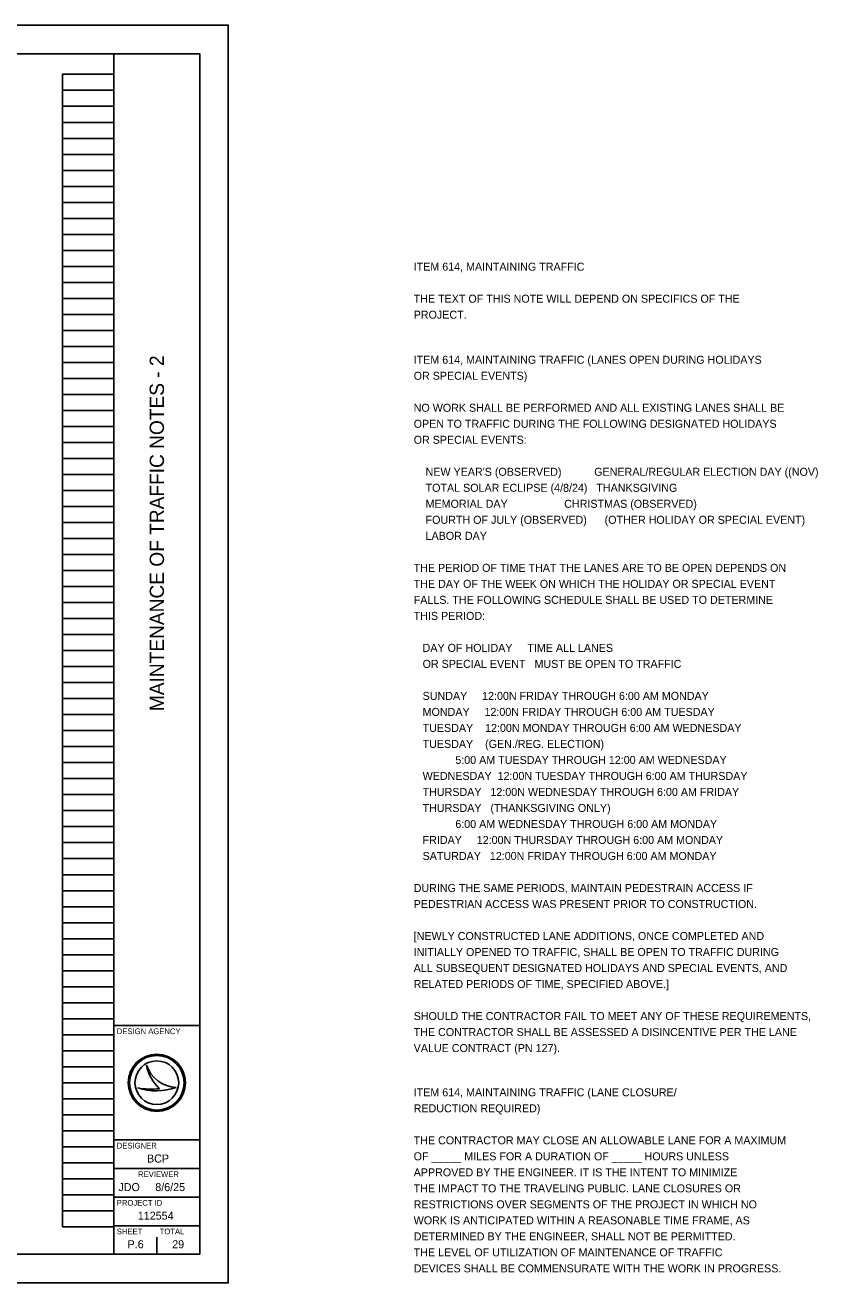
# Model space of a CAD drawing. Extents: x -59 to 65, y -12 to 46.
# Drawn here: x 30.45 to 44.31, y 0 to 22 of the extents above; entities that cross this region are included whole.
import ezdxf

# ---------------------------------------------------------------- set-up
doc = ezdxf.new("R2010")
doc.units = 0
for name, color, linetype in [('SH_Border', 7, 'Continuous'), ('SH_Cut_Line', 7, 'Continuous'), ('SH_Data', 7, 'Continuous'), ('SH_Text', 7, 'Continuous')]:
    doc.layers.add(name, color=color, linetype=linetype)

msp = doc.modelspace()

# ---------------------------------------------------------------- linework, layer by layer
at = {"layer": 'SH_Border'}
for p, q in [((32, 0.5), (32, 21.5)), ((32, 4.5), (33.5, 4.5)), ((32, 2.5), (33.5, 2.5)), ((32, 2), (33.5, 2)), ((32, 1.5), (33.5, 1.5)), ((32, 1), (33.5, 1))]:
    msp.add_line(p, q, dxfattribs=at)
msp.add_lwpolyline([(1.5, 21.5), (33.5, 21.5), (33.5, 0.5), (1.5, 0.5)], close=True, dxfattribs=at)
at = {"layer": 'SH_Cut_Line'}
msp.add_lwpolyline([(0, 0), (34, 0), (34, 22), (0, 22)], close=True, dxfattribs=at)
at = {"layer": 'SH_Data'}
for p, q in [((31.1, 0.98), (31.1, 21.14)), ((31.1, 21.14), (32, 21.14)), ((32, 0.98), (32, 21.14)), ((31.1, 20.86), (32, 20.86)), ((31.1, 20.58), (32, 20.58)), ((31.1, 20.3), (32, 20.3)), ((31.1, 20.02), (32, 20.02)), ((31.1, 19.74), (32, 19.74)), ((31.1, 19.46), (32, 19.46)), ((31.1, 19.18), (32, 19.18)), ((31.1, 18.9), (32, 18.9)), ((31.1, 18.62), (32, 18.62)), ((31.1, 18.34), (32, 18.34)), ((31.1, 18.06), (32, 18.06)), ((31.1, 17.78), (32, 17.78)), ((31.1, 17.5), (32, 17.5)), ((31.1, 17.22), (32, 17.22)), ((31.1, 16.94), (32, 16.94)), ((31.1, 16.66), (32, 16.66)), ((31.1, 16.38), (32, 16.38)), ((31.1, 16.1), (32, 16.1)), ((31.1, 15.82), (32, 15.82)), ((31.1, 15.54), (32, 15.54)), ((31.1, 15.26), (32, 15.26)), ((31.1, 14.98), (32, 14.98)), ((31.1, 14.7), (32, 14.7)), ((31.1, 14.42), (32, 14.42)), ((31.1, 14.14), (32, 14.14)), ((31.1, 13.86), (32, 13.86)), ((31.1, 13.58), (32, 13.58)), ((31.1, 13.3), (32, 13.3)), ((31.1, 13.02), (32, 13.02)), ((31.1, 12.74), (32, 12.74)), ((31.1, 12.46), (32, 12.46)), ((31.1, 12.18), (32, 12.18)), ((31.1, 11.9), (32, 11.9)), ((31.1, 11.62), (32, 11.62)), ((31.1, 11.34), (32, 11.34)), ((31.1, 11.06), (32, 11.06)), ((31.1, 10.78), (32, 10.78)), ((31.1, 10.5), (32, 10.5)), ((31.1, 10.22), (32, 10.22)), ((31.1, 9.94), (32, 9.94)), ((31.1, 9.66), (32, 9.66)), ((31.1, 9.38), (32, 9.38)), ((31.1, 9.1), (32, 9.1)), ((31.1, 8.82), (32, 8.82)), ((31.1, 8.54), (32, 8.54)), ((31.1, 8.26), (32, 8.26)), ((31.1, 7.98), (32, 7.98)), ((31.1, 7.7), (32, 7.7)), ((31.1, 7.42), (32, 7.42)), ((31.1, 7.14), (32, 7.14)), ((31.1, 6.86), (32, 6.86)), ((31.1, 6.58), (32, 6.58)), ((31.1, 6.3), (32, 6.3)), ((31.1, 6.02), (32, 6.02)), ((31.1, 5.74), (32, 5.74)), ((31.1, 5.46), (32, 5.46)), ((31.1, 5.18), (32, 5.18)), ((31.1, 4.9), (32, 4.9)), ((31.1, 4.62), (32, 4.62)), ((31.1, 4.34), (32, 4.34)), ((31.1, 4.06), (32, 4.06)), ((31.1, 3.78), (32, 3.78)), ((32.567, 3.81), (32.567, 3.81)), ((31.1, 3.5), (32, 3.5)), ((32.417, 3.41), (32.417, 3.41)), ((32.75, 3.5), (32.75, 3.5)), ((33.087, 3.419), (33.087, 3.419)), ((31.1, 3.22), (32, 3.22)), ((31.1, 2.94), (32, 2.94)), ((31.1, 2.66), (32, 2.66)), ((31.1, 2.38), (32, 2.38)), ((31.1, 2.1), (32, 2.1)), ((31.1, 1.82), (32, 1.82)), ((31.1, 1.54), (32, 1.54)), ((31.1, 1.26), (32, 1.26)), ((31.1, 0.98), (32, 0.98)), ((32.375, 0.675), (32.375, 0.675)), ((32.75, 0.5), (32.75, 0.8))]:
    msp.add_line(p, q, dxfattribs=at)
for radius in [0.5, 0.477, 0.477, 0.382]:
    msp.add_circle((32.75, 3.5), radius, dxfattribs=at)
for centre, radius, start, end in [((33.116, 3.998), 0.58, 198.9257, 198.9319), ((33.347, 3.97), 0.796, 191.6379, 191.6421), ((33.116, 3.998), 0.58, 198.9319, 267.1657), ((33.347, 3.97), 0.796, 191.6421, 226.0947), ((32.739, 4.37), 1.013, 251.4576, 290.0832), ((32.648, 4.654), 1.266, 259.4964, 259.4995), ((32.739, 4.37), 1.013, 251.4527, 251.4576), ((32.648, 4.654), 1.266, 259.4995, 276.6672)]:
    msp.add_arc(centre, radius, start, end, dxfattribs=at)

# ---------------------------------------------------------------- texts
msp.add_text('MAINTENANCE OF TRAFFIC NOTES - 2', height=0.25, rotation=90, dxfattribs=at).set_placement((32.875, 10.001))
for s, height, p in [('DESIGN AGENCY', 0.1, (32.05, 4.35)), ('DESIGNER', 0.1, (32.05, 2.35)), ('BCP', 0.14, (32.579, 2.105)), ('REVIEWER', 0.1, (32.422, 1.85)), ('JDO', 0.14, (32.079, 1.605)), ('8/6/25', 0.14, (32.723, 1.605)), ('PROJECT ID', 0.1, (32.05, 1.35)), ('112554', 0.14, (32.418, 1.105)), ('SHEET', 0.1, (32.05, 0.85)), ('TOTAL', 0.1, (32.8, 0.85)), ('P.6', 0.14, (32.239, 0.605)), ('29', 0.14, (33.019, 0.605))]:
    msp.add_text(s, height=height, dxfattribs=at).set_placement(p)
at = {"layer": 'SH_Text'}
for s, p in [('ITEM 614, MAINTAINING TRAFFIC', (37.241, 17.705)), ('THE TEXT OF THIS NOTE WILL DEPEND ON SPECIFICS OF THE', (37.241, 17.145)), ('PROJECT.', (37.241, 16.865)), ('ITEM 614, MAINTAINING TRAFFIC (LANES OPEN DURING HOLIDAYS', (37.241, 16.077)), ('OR SPECIAL EVENTS)', (37.241, 15.797)), ('NO WORK SHALL BE PERFORMED AND ALL EXISTING LANES SHALL BE', (37.241, 15.237)), ('OPEN TO TRAFFIC DURING THE FOLLOWING DESIGNATED HOLIDAYS', (37.241, 14.957)), ('OR SPECIAL EVENTS:', (37.241, 14.677)), ("    NEW YEAR'S (OBSERVED)           GENERAL/REGULAR ELECTION DAY ((NOV)", (37.241, 14.117)), ('    TOTAL SOLAR ECLIPSE (4/8/24)   THANKSGIVING', (37.241, 13.837)), ('    MEMORIAL DAY                   CHRISTMAS (OBSERVED)', (37.241, 13.557)), ('    FOURTH OF JULY (OBSERVED)      (OTHER HOLIDAY OR SPECIAL EVENT)', (37.241, 13.277)), ('    LABOR DAY', (37.241, 12.997)), ('THE PERIOD OF TIME THAT THE LANES ARE TO BE OPEN DEPENDS ON', (37.241, 12.437)), ('THE DAY OF THE WEEK ON WHICH THE HOLIDAY OR SPECIAL EVENT', (37.241, 12.157)), ('FALLS. THE FOLLOWING SCHEDULE SHALL BE USED TO DETERMINE', (37.241, 11.877)), ('THIS PERIOD:', (37.241, 11.597)), ('   DAY OF HOLIDAY     TIME ALL LANES', (37.241, 11.037)), ('   OR SPECIAL EVENT   MUST BE OPEN TO TRAFFIC', (37.241, 10.757)), ('   SUNDAY     12:00N FRIDAY THROUGH 6:00 AM MONDAY', (37.241, 10.197)), ('   MONDAY     12:00N FRIDAY THROUGH 6:00 AM TUESDAY', (37.241, 9.917)), ('   TUESDAY    12:00N MONDAY THROUGH 6:00 AM WEDNESDAY', (37.241, 9.637)), ('   TUESDAY    (GEN./REG. ELECTION)', (37.241, 9.357)), ('              5:00 AM TUESDAY THROUGH 12:00 AM WEDNESDAY', (37.241, 9.077)), ('   WEDNESDAY  12:00N TUESDAY THROUGH 6:00 AM THURSDAY', (37.241, 8.797)), ('   THURSDAY   12:00N WEDNESDAY THROUGH 6:00 AM FRIDAY', (37.241, 8.517)), ('   THURSDAY   (THANKSGIVING ONLY)', (37.241, 8.237)), ('              6:00 AM WEDNESDAY THROUGH 6:00 AM MONDAY', (37.241, 7.957)), ('   FRIDAY     12:00N THURSDAY THROUGH 6:00 AM MONDAY', (37.241, 7.677)), ('   SATURDAY   12:00N FRIDAY THROUGH 6:00 AM MONDAY', (37.241, 7.397)), ('DURING THE SAME PERIODS, MAINTAIN PEDESTRAIN ACCESS IF', (37.241, 6.837)), ('PEDESTRIAN ACCESS WAS PRESENT PRIOR TO CONSTRUCTION.', (37.241, 6.557)), ('[NEWLY CONSTRUCTED LANE ADDITIONS, ONCE COMPLETED AND', (37.241, 5.997)), ('INITIALLY OPENED TO TRAFFIC, SHALL BE OPEN TO TRAFFIC DURING', (37.241, 5.717)), ('ALL SUBSEQUENT DESIGNATED HOLIDAYS AND SPECIAL EVENTS, AND', (37.241, 5.437)), ('RELATED PERIODS OF TIME, SPECIFIED ABOVE.]', (37.241, 5.157)), ('SHOULD THE CONTRACTOR FAIL TO MEET ANY OF THESE REQUIREMENTS,', (37.241, 4.597)), ('THE CONTRACTOR SHALL BE ASSESSED A DISINCENTIVE PER THE LANE', (37.241, 4.317)), ('VALUE CONTRACT (PN 127).', (37.241, 4.037)), ('ITEM 614, MAINTAINING TRAFFIC (LANE CLOSURE/', (37.241, 3.263)), ('REDUCTION REQUIRED)', (37.241, 2.983)), ('THE CONTRACTOR MAY CLOSE AN ALLOWABLE LANE FOR A MAXIMUM', (37.241, 2.423)), ('OF _____ MILES FOR A DURATION OF _____ HOURS UNLESS', (37.241, 2.143)), ('APPROVED BY THE ENGINEER. IT IS THE INTENT TO MINIMIZE', (37.241, 1.863)), ('THE IMPACT TO THE TRAVELING PUBLIC. LANE CLOSURES OR', (37.241, 1.583)), ('RESTRICTIONS OVER SEGMENTS OF THE PROJECT IN WHICH NO', (37.241, 1.303)), ('WORK IS ANTICIPATED WITHIN A REASONABLE TIME FRAME, AS', (37.241, 1.023)), ('DETERMINED BY THE ENGINEER, SHALL NOT BE PERMITTED.', (37.241, 0.743)), ('THE LEVEL OF UTILIZATION OF MAINTENANCE OF TRAFFIC', (37.241, 0.463)), ('DEVICES SHALL BE COMMENSURATE WITH THE WORK IN PROGRESS.', (37.241, 0.183))]:
    msp.add_text(s, height=0.14, dxfattribs=at).set_placement(p)

doc.saveas('drawing.dxf')
